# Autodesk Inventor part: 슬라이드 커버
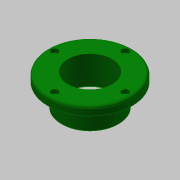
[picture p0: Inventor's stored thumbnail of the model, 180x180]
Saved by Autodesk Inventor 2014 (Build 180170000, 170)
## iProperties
Created: 2015-10
Part Number: 슬라이드 커버
Document SubType Name: Modeling
Designer: mdu
Density: 2.71 g/cm^3
Material: Aluminum 6061
Mass: 221.924 g
Surface Area: 243.242 cm^2
Volume: 81.8907 cm^3
Appearance: Dark Green
Author: mdu
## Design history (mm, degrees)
sketch "스케치1"
  geometry: C1 r 47.5 at (0, 0); C2 r 32.5 at (0, 0); 1 further point
  constraints: 2 centre point, 2 coincident
  dimensions: "d33" = 95 diameter of C1; "d35" = 65 diameter of C2
extrude "돌출1" new body sketch "스케치1" distance "d0" = 10; taper "d1" = 0 deg
extrude "돌출2" join sketch "스케치1" distance "d2" = 26; taper "d3" = 0 deg
hole "구멍1" diameter "d6" = 50; stored, may be unused: countersink angle "d10" = 90 deg, drill point angle "d12" = 118 deg; dims "d4" = 10, "d5" = 10, "d7" = 6, "d8" = 4, "d9" = 2, "d11" = 8
sketch "스케치2" dims "d36" = 80
  geometry: 4 further points
  constraints: 2 coincident, 2 vertical alignment, 2 other
hole "구멍2" sketch "스케치2" at (0, 40) diameter "d13" = 4.5; stored, may be unused: countersink angle "d17" = 90 deg, drill point angle "d19" = 118 deg; dims "d14" = 6, "d15" = 8, "d16" = 4.4, "d18" = 8
fillet "모깎기1" dims "d23" = 3
chamfer "모따기1" distance "d24" = 1; stored, may be unused: second distance "d25" = 2, angle "d26" = 45 deg
sketch "스케치3"
  geometry: C1 r 25 at (0, 0); C2 r 30 at (0, 0); C3 r 26 at (0, 0) reference; 1 further point
  constraints: 2 centre point, 2 coincident
  dimensions: "d27" = 60 diameter of C2
extrude "돌출3" cut sketch "스케치3" distance "d28" = 3; taper "d29" = 0 deg
chamfer "모따기2" distance "d30" = 1; stored, may be unused: second distance "d31" = 2, angle "d32" = 45 deg
node "솔리드1"
pattern_circular "원형 패턴1" dims angle "d21" = 360 deg
